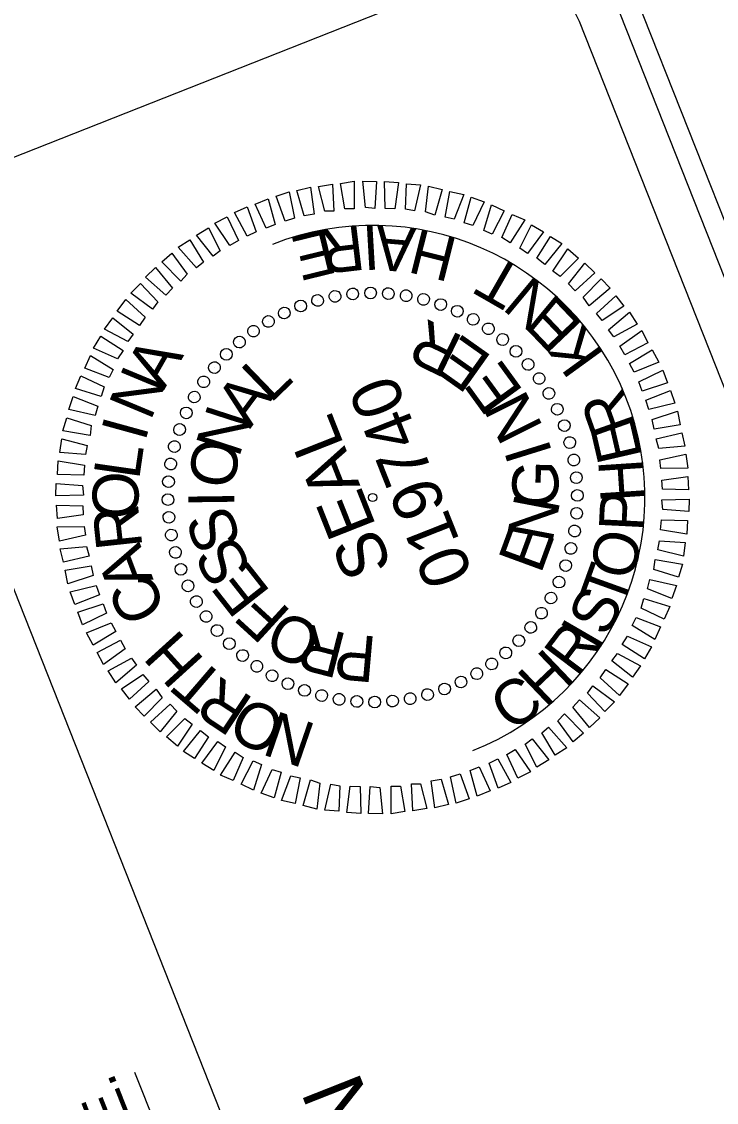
# Model space of a CAD drawing. Extents: x 1247235 to 1260080, y 742320 to 754020.
# Drawn here: x 1251748 to 1252131, y 750320 to 750916 of the extents above; entities that cross this region are included whole.
import ezdxf

# ---------------------------------------------------------------- set-up
doc = ezdxf.new("R2010")
doc.units = 0
for name, color, linetype in [('Scratch_Level_0', 7, 'Continuous'), ('Scratch_Level_1', 7, 'Continuous'), ('Sheet Plot Border Inside CELL', 7, 'Continuous'), ('Sheet Professional Seal CELL', 7, 'Continuous'), ('Sheet Title CELL', 7, 'Continuous')]:
    doc.layers.add(name, color=color, linetype=linetype)

msp = doc.modelspace()

# ---------------------------------------------------------------- linework, layer by layer
at = {"layer": 'Scratch_Level_0'}
msp.add_circle((1251941.28, 750653.8), 2.25, dxfattribs=at)
msp.add_arc((1251941.28, 750653.8), 150.14, 291.57435, 111.57435, dxfattribs=at)
at = {"layer": 'Scratch_Level_1'}
msp.add_line((1251941.28, 750653.8), (1251941.28, 750653.8), dxfattribs=at)
at = {"layer": 'Sheet Plot Border Inside CELL'}
msp.add_lwpolyline([(1254509.01, 744803.37), (1251751.47, 751777.23), (1247336.16, 750031.37), (1250093.7, 743057.51)], close=True, dxfattribs=at)
at = {"layer": 'Sheet Professional Seal CELL'}
for p, q in [((1251920.66, 750764.68), (1251920.66, 750764.68)), ((1251930.2, 750766.27), (1251930.2, 750766.27)), ((1251940.14, 750766.82), (1251940.14, 750766.82)), ((1251950, 750766.36), (1251950, 750766.36)), ((1251959.82, 750765.4), (1251959.82, 750765.4)), ((1251969.42, 750763.15), (1251969.42, 750763.15)), ((1251901.63, 750759.58), (1251901.63, 750759.58)), ((1251911.09, 750762.59), (1251911.09, 750762.59)), ((1251978.97, 750760.4), (1251978.97, 750760.4)), ((1251892.51, 750755.73), (1251892.51, 750755.73)), ((1251987.94, 750756.69), (1251987.94, 750756.69)), ((1251996.95, 750752.26), (1251996.95, 750752.26)), ((1251875.46, 750745.6), (1251875.46, 750745.6)), ((1251884.01, 750750.91), (1251884.01, 750750.91)), ((1252005.08, 750747.01), (1252005.08, 750747.01)), ((1251867.67, 750739.61), (1251867.67, 750739.61)), ((1252013.03, 750740.96), (1252013.03, 750740.96)), ((1252020.44, 750734.45), (1252020.44, 750734.45)), ((1251860.62, 750732.96), (1251860.62, 750732.96)), ((1252027.1, 750727.41), (1252027.1, 750727.41)), ((1251854.12, 750725.55), (1251854.12, 750725.55)), ((1251848.07, 750717.59), (1251848.07, 750717.59)), ((1252033.09, 750719.61), (1252033.09, 750719.61)), ((1251842.81, 750709.46), (1251842.81, 750709.46)), ((1252038.4, 750711.07), (1252038.4, 750711.07)), ((1251838.39, 750700.46), (1251838.39, 750700.46)), ((1252043.21, 750702.57), (1252043.21, 750702.57)), ((1252047.06, 750693.44), (1252047.06, 750693.44)), ((1251834.68, 750691.49), (1251834.68, 750691.49)), ((1251831.93, 750681.93), (1251831.93, 750681.93)), ((1252050.08, 750683.99), (1252050.08, 750683.99)), ((1252052.17, 750674.41), (1252052.17, 750674.41)), ((1251829.67, 750672.33), (1251829.67, 750672.33)), ((1251828.72, 750662.51), (1251828.72, 750662.51)), ((1252053.76, 750664.88), (1252053.76, 750664.88)), ((1251828.26, 750652.66), (1251828.26, 750652.66)), ((1251941.28, 750653.8), (1251941.28, 750653.8)), ((1252054.31, 750654.93), (1252054.31, 750654.93)), ((1252053.85, 750645.08), (1252053.85, 750645.08)), ((1251828.8, 750642.71), (1251828.8, 750642.71)), ((1251830.4, 750633.18), (1251830.4, 750633.18)), ((1252052.89, 750635.26), (1252052.89, 750635.26)), ((1251832.49, 750623.6), (1251832.49, 750623.6)), ((1252050.64, 750625.66), (1252050.64, 750625.66)), ((1251835.5, 750614.15), (1251835.5, 750614.15)), ((1252047.89, 750616.1), (1252047.89, 750616.1)), ((1251839.35, 750605.02), (1251839.35, 750605.02)), ((1252044.17, 750607.13), (1252044.17, 750607.13)), ((1251844.16, 750596.52), (1251844.16, 750596.52)), ((1252039.75, 750598.13), (1252039.75, 750598.13)), ((1251849.48, 750587.98), (1251849.48, 750587.98)), ((1252034.5, 750590), (1252034.5, 750590)), ((1251855.46, 750580.18), (1251855.46, 750580.18)), ((1252028.45, 750582.04), (1252028.45, 750582.04)), ((1251862.12, 750573.14), (1251862.12, 750573.14)), ((1252021.94, 750574.63), (1252021.94, 750574.63)), ((1251869.53, 750566.63), (1251869.53, 750566.63)), ((1252014.9, 750567.98), (1252014.9, 750567.98)), ((1251877.49, 750560.58), (1251877.49, 750560.58)), ((1252007.1, 750561.99), (1252007.1, 750561.99)), ((1251885.62, 750555.33), (1251885.62, 750555.33)), ((1251998.56, 750556.68), (1251998.56, 750556.68)), ((1251894.62, 750550.9), (1251894.62, 750550.9)), ((1251990.06, 750551.86), (1251990.06, 750551.86)), ((1251903.59, 750547.19), (1251903.59, 750547.19)), ((1251913.15, 750544.44), (1251913.15, 750544.44)), ((1251961.9, 750542.91), (1251961.9, 750542.91)), ((1251971.48, 750545), (1251971.48, 750545)), ((1251980.93, 750548.01), (1251980.93, 750548.01)), ((1251922.75, 750542.19), (1251922.75, 750542.19)), ((1251932.56, 750541.23), (1251932.56, 750541.23)), ((1251942.42, 750540.77), (1251942.42, 750540.77)), ((1251952.37, 750541.32), (1251952.37, 750541.32))]:
    msp.add_line(p, q, dxfattribs=at)
for points in [[(1251903.54, 750809.21), (1251899.5, 750823.09), (1251906.95, 750825.07), (1251908.98, 750810.15)], [(1251914.88, 750811.75), (1251911.42, 750825.39), (1251919.11, 750826.73), (1251919.93, 750811.81)], [(1251925.99, 750813), (1251923.59, 750827.05), (1251931.07, 750828.32), (1251931.05, 750813.07)], [(1251937.28, 750813.84), (1251935.92, 750828.3), (1251943.48, 750828.14), (1251942.58, 750813.27)], [(1251948.14, 750813.29), (1251947.82, 750828.17), (1251955.55, 750827.59), (1251953.57, 750813.02)], [(1251959.42, 750812.91), (1251959.93, 750826.91), (1251967.66, 750826.33), (1251964.39, 750811.97)], [(1251970.4, 750811.45), (1251972.05, 750825.65), (1251979.56, 750823.78), (1251975.49, 750809.59)], [(1251882.54, 750802.35), (1251876.54, 750815.71), (1251883.65, 750818.52), (1251887.56, 750804.34)], [(1251893.09, 750806.28), (1251888.13, 750820.05), (1251895.2, 750822.36), (1251898.27, 750807.85)], [(1251981.25, 750808.48), (1251983.9, 750822.59), (1251991.54, 750821.02), (1251986.31, 750807.33)], [(1251991.69, 750805.35), (1251995.55, 750819.45), (1252002.81, 750817), (1251996.61, 750803.91)], [(1251872.16, 750798.01), (1251865.11, 750810.95), (1251872.06, 750814.18), (1251877.02, 750800.41)], [(1252002.53, 750801.17), (1252006.89, 750815.23), (1252013.77, 750811.9), (1252007.21, 750799.14)], [(1251862.62, 750792.78), (1251854.31, 750805.22), (1251861.17, 750808.66), (1251867.31, 750795.6)], [(1252012.59, 750797.16), (1252018.15, 750810.01), (1252025.16, 750806.97), (1252017.09, 750794.34)], [(1251853.32, 750786.93), (1251844.13, 750798.54), (1251850.75, 750802.6), (1251857.21, 750789.92)], [(1252022.38, 750791.35), (1252028.87, 750804.32), (1252035.5, 750800.41), (1252026.67, 750788.45)], [(1251844.27, 750780.44), (1251834.16, 750791.93), (1251840.57, 750795.92), (1251848.08, 750783.65)], [(1252031.8, 750785.88), (1252039.41, 750797.85), (1252045.54, 750793.98), (1252036.13, 750782.27)], [(1251835.55, 750773.13), (1251825.06, 750783.74), (1251830.64, 750788.6), (1251839.11, 750776.95)], [(1252040.68, 750778.75), (1252048.91, 750790.96), (1252054.83, 750785.79), (1252044.76, 750775.76)], [(1252049.25, 750771.74), (1252058.32, 750783.06), (1252063.82, 750777.74), (1252052.96, 750767.88)], [(1251827.2, 750765.47), (1251816.04, 750775.33), (1251821.66, 750780.7), (1251830.98, 750769.38)], [(1251819.86, 750757.73), (1251807.9, 750766.55), (1251813.31, 750771.83), (1251822.84, 750761.81)], [(1252057.29, 750764.27), (1252067.27, 750774.5), (1252072.27, 750769.22), (1252060.61, 750759.53)], [(1252064.69, 750755.34), (1252075.34, 750765.11), (1252079.79, 750759.37), (1252067.89, 750751.52)], [(1251812.8, 750748.65), (1251800.47, 750756.59), (1251805.17, 750763.05), (1251815.83, 750753.23)], [(1251806.38, 750739.82), (1251793.53, 750746.59), (1251798.03, 750752.97), (1251809.36, 750743.9)], [(1252071.38, 750746.37), (1252082.83, 750755.98), (1252087.1, 750749.44), (1252074.17, 750742.39)], [(1252077.65, 750737.24), (1252089.72, 750745.88), (1252093.08, 750739.22), (1252080.27, 750732.46)], [(1251800.7, 750730.31), (1251787.48, 750736.21), (1251791.39, 750742.84), (1251803.72, 750734.9)], [(1252082.88, 750727.69), (1252095.36, 750735.29), (1252099.01, 750728.5), (1252085.49, 750722.92)], [(1251796.06, 750720.01), (1251782.67, 750725.12), (1251785.71, 750732.13), (1251798.17, 750724.47)], [(1252088.06, 750717.64), (1252101.25, 750724.06), (1252103.77, 750717.08), (1252089.84, 750712.54)], [(1251791.72, 750709.58), (1251777.44, 750713.86), (1251780.48, 750720.87), (1251793.28, 750714.8)], [(1251788.37, 750699.07), (1251773.8, 750702.26), (1251776.26, 750709.52), (1251789.73, 750704.2)], [(1252091.83, 750707.51), (1252105.43, 750712.89), (1252107.95, 750705.91), (1252093.6, 750702.41)], [(1251785.49, 750688.01), (1251770.46, 750690.53), (1251772.7, 750697.71), (1251786.18, 750693.6)], [(1252095.34, 750696.8), (1252109.27, 750701.35), (1252110.74, 750693.94), (1252096.48, 750691.45)], [(1251783.07, 750677.61), (1251768.91, 750678.54), (1251769.98, 750686.23), (1251784, 750682.58)], [(1252097.63, 750686.1), (1252111.77, 750689.51), (1252113.45, 750682.19), (1252098.99, 750680.83)], [(1251782.06, 750666.08), (1251767.65, 750666.43), (1251768.01, 750674.08), (1251782.54, 750671.6)], [(1252099.55, 750674.52), (1252113.98, 750677.8), (1252115.12, 750670.03), (1252100.24, 750669.71)], [(1252100.8, 750663.4), (1252115.02, 750665.39), (1252115.49, 750658.08), (1252101.07, 750658.43)], [(1251781.81, 750655.1), (1251766.72, 750654.7), (1251766.92, 750661.55), (1251781.37, 750660.49)], [(1252100.76, 750652.49), (1252115.84, 750652.89), (1252115.65, 750646.04), (1252101.2, 750647.1)], [(1251781.76, 750644.19), (1251767.55, 750642.2), (1251767.08, 750649.51), (1251781.49, 750649.16)], [(1252100.51, 750641.51), (1252114.92, 750641.16), (1252114.55, 750633.51), (1252100.02, 750635.99)], [(1251783.01, 750633.07), (1251768.59, 750629.79), (1251767.45, 750637.56), (1251782.32, 750637.88)], [(1251784.93, 750621.49), (1251770.8, 750618.08), (1251769.11, 750625.4), (1251783.57, 750626.76)], [(1252099.5, 750629.98), (1252113.66, 750629.05), (1252112.58, 750621.36), (1252098.56, 750625.01)], [(1251787.23, 750610.79), (1251773.3, 750606.24), (1251771.82, 750613.65), (1251786.08, 750616.14)], [(1252097.08, 750619.59), (1252112.11, 750617.06), (1252109.87, 750609.88), (1252096.39, 750613.99)], [(1252094.19, 750608.52), (1252108.76, 750605.33), (1252106.31, 750598.07), (1252092.83, 750603.39)], [(1251790.74, 750600.08), (1251777.14, 750594.7), (1251774.62, 750601.69), (1251788.96, 750605.18)], [(1252090.85, 750598.01), (1252105.12, 750593.73), (1252102.09, 750586.72), (1252089.28, 750592.79)], [(1251794.5, 750589.95), (1251781.31, 750583.53), (1251778.79, 750590.51), (1251792.72, 750595.05)], [(1251799.68, 750579.9), (1251787.2, 750572.3), (1251783.55, 750579.09), (1251797.07, 750584.67)], [(1252086.5, 750587.58), (1252099.9, 750582.47), (1252096.86, 750575.46), (1252084.4, 750583.12)], [(1251804.91, 750570.35), (1251792.84, 750561.71), (1251789.49, 750568.37), (1251802.3, 750575.13)], [(1252081.87, 750577.28), (1252095.09, 750571.38), (1252091.18, 750564.75), (1252078.84, 750572.69)], [(1252076.19, 750567.77), (1252089.03, 750561), (1252084.54, 750554.62), (1252073.21, 750563.69)], [(1251811.18, 750561.22), (1251799.74, 750551.61), (1251795.46, 750558.15), (1251808.4, 750565.2)], [(1251817.87, 750552.25), (1251807.22, 750542.48), (1251802.78, 750548.22), (1251814.67, 750556.07)], [(1252069.76, 750558.94), (1252082.1, 750551), (1252077.39, 750544.54), (1252066.74, 750554.36)], [(1252062.71, 750549.86), (1252074.66, 750541.04), (1252069.25, 750535.76), (1252059.72, 750545.78)], [(1251825.28, 750543.32), (1251815.29, 750533.09), (1251810.3, 750538.37), (1251821.95, 750548.06)], [(1251833.31, 750535.86), (1251824.24, 750524.53), (1251818.75, 750529.85), (1251829.61, 750539.71)], [(1252055.36, 750542.12), (1252066.52, 750532.26), (1252060.9, 750526.89), (1252051.59, 750538.21)], [(1251841.89, 750528.84), (1251833.65, 750516.63), (1251827.74, 750521.8), (1251837.81, 750531.83)], [(1252047.02, 750534.47), (1252057.51, 750523.85), (1252051.93, 750518.99), (1252043.45, 750530.64)], [(1251850.76, 750521.71), (1251843.15, 750509.74), (1251837.02, 750513.61), (1251846.43, 750525.32)], [(1252038.3, 750527.15), (1252048.41, 750515.66), (1252042, 750511.67), (1252034.48, 750523.94)], [(1251860.18, 750516.24), (1251853.7, 750503.27), (1251847.07, 750507.18), (1251855.89, 750519.14)], [(1252029.25, 750520.66), (1252038.44, 750509.05), (1252031.82, 750504.99), (1252025.35, 750517.67)], [(1251869.98, 750510.43), (1251864.41, 750497.59), (1251857.4, 750500.62), (1251865.48, 750513.25)], [(1252019.95, 750514.81), (1252028.26, 750502.37), (1252021.39, 750498.93), (1252015.26, 750511.99)], [(1251880.03, 750506.42), (1251875.67, 750492.36), (1251868.79, 750495.69), (1251875.36, 750508.45)], [(1252010.4, 750509.58), (1252017.45, 750496.64), (1252010.51, 750493.41), (1252005.55, 750507.18)], [(1251890.88, 750502.24), (1251887.02, 750488.14), (1251879.76, 750490.59), (1251885.95, 750503.68)], [(1251989.48, 750501.31), (1251994.44, 750487.54), (1251987.37, 750485.23), (1251984.29, 750499.74)], [(1252000.02, 750505.24), (1252006.03, 750491.88), (1251998.92, 750489.07), (1251995, 750503.25)], [(1251901.31, 750499.11), (1251898.66, 750485), (1251891.02, 750486.57), (1251896.26, 750500.26)], [(1251912.16, 750496.14), (1251910.52, 750481.94), (1251903.01, 750483.81), (1251907.07, 750498)], [(1251923.15, 750494.68), (1251922.63, 750480.68), (1251914.9, 750481.26), (1251918.18, 750495.62)], [(1251967.69, 750495.84), (1251971.15, 750482.2), (1251963.45, 750480.86), (1251962.63, 750495.78)], [(1251979.02, 750498.38), (1251983.06, 750484.5), (1251975.62, 750482.52), (1251973.59, 750497.45)], [(1251934.42, 750494.3), (1251934.74, 750479.42), (1251927.01, 750480), (1251928.99, 750494.57)], [(1251945.29, 750493.76), (1251946.65, 750479.29), (1251939.09, 750479.45), (1251939.98, 750494.32)], [(1251956.57, 750494.59), (1251958.98, 750480.54), (1251951.5, 750479.27), (1251951.51, 750494.52)]]:
    msp.add_lwpolyline(points, close=True, dxfattribs=at)
for centre, major_axis in [((1251930.32, 750766.12), (-0.31, 3.22)), ((1251940.15, 750766.65), (-0.03, 3.24)), ((1251949.99, 750766.32), (0.25, 3.23)), ((1251901.62, 750759.46), (-1.14, 3.03)), ((1251910.98, 750762.51), (-0.87, 3.12)), ((1251920.57, 750764.74), (-0.59, 3.18)), ((1251959.77, 750765.13), (0.53, 3.2)), ((1251969.4, 750763.1), (0.81, 3.14)), ((1251978.82, 750760.23), (1.08, 3.06)), ((1251892.56, 750755.6), (-1.4, 2.92)), ((1251987.95, 750756.55), (1.34, 2.95)), ((1251883.88, 750750.96), (-1.65, 2.79)), ((1251996.73, 750752.1), (1.59, 2.82)), ((1251875.63, 750745.59), (-1.88, 2.64)), ((1252005.09, 750746.89), (1.83, 2.67)), ((1251867.87, 750739.52), (-2.11, 2.46)), ((1252012.96, 750740.97), (2.06, 2.5)), ((1251860.68, 750732.8), (-2.31, 2.27)), ((1252020.28, 750734.4), (2.27, 2.31)), ((1251854.1, 750725.47), (-2.5, 2.06)), ((1252027.01, 750727.2), (2.46, 2.11)), ((1252033.08, 750719.45), (2.64, 1.88)), ((1251848.19, 750717.6), (-2.67, 1.83)), ((1251842.98, 750709.24), (-2.82, 1.59)), ((1252038.45, 750711.2), (2.79, 1.65)), ((1251838.52, 750700.46), (-2.95, 1.34)), ((1252043.09, 750702.51), (2.92, 1.4)), ((1251834.85, 750691.33), (-3.06, 1.08)), ((1252046.94, 750693.46), (3.03, 1.14)), ((1252050, 750684.1), (3.12, 0.87)), ((1251831.98, 750681.91), (-3.14, 0.81)), ((1251829.95, 750672.28), (-3.2, 0.53)), ((1252052.23, 750674.51), (3.18, 0.59)), ((1252053.61, 750664.76), (3.22, 0.31)), ((1251828.76, 750662.5), (-3.23, 0.25)), ((1251828.43, 750652.66), (-3.24, -0.03)), ((1252054.14, 750654.93), (3.24, 0.03)), ((1251828.96, 750642.83), (-3.22, -0.31)), ((1252053.81, 750645.09), (3.23, -0.25)), ((1252052.62, 750635.31), (3.2, -0.53)), ((1251830.34, 750633.08), (-3.18, -0.59)), ((1251832.57, 750623.49), (-3.12, -0.87)), ((1252050.58, 750625.68), (3.14, -0.81)), ((1251835.62, 750614.13), (-3.03, -1.14)), ((1252047.72, 750616.26), (3.06, -1.08)), ((1251839.48, 750605.08), (-2.92, -1.4)), ((1252044.04, 750607.13), (2.95, -1.34)), ((1251844.11, 750596.39), (-2.79, -1.65)), ((1252039.58, 750598.35), (2.82, -1.59)), ((1251849.49, 750588.14), (-2.64, -1.88)), ((1252034.38, 750589.99), (2.67, -1.83)), ((1252028.46, 750582.12), (2.5, -2.06)), ((1251855.56, 750580.39), (-2.46, -2.11)), ((1252021.88, 750574.8), (2.31, -2.27)), ((1251862.28, 750573.2), (-2.27, -2.31)), ((1251869.61, 750566.62), (-2.06, -2.5)), ((1252014.69, 750568.07), (2.11, -2.46)), ((1251877.48, 750560.7), (-1.83, -2.67)), ((1252006.94, 750562), (1.88, -2.64)), ((1251885.84, 750555.49), (-1.59, -2.82)), ((1251894.61, 750551.04), (-1.34, -2.95)), ((1251990, 750551.99), (1.4, -2.92)), ((1251998.69, 750556.63), (1.65, -2.79)), ((1251903.75, 750547.36), (-1.08, -3.06)), ((1251971.58, 750545.08), (0.87, -3.12)), ((1251980.94, 750548.13), (1.14, -3.03)), ((1251913.17, 750544.49), (-0.81, -3.14)), ((1251922.8, 750542.46), (-0.53, -3.2)), ((1251932.57, 750541.27), (-0.25, -3.23)), ((1251942.41, 750540.94), (0.03, -3.24)), ((1251952.25, 750541.47), (0.31, -3.22)), ((1251961.99, 750542.85), (0.59, -3.18))]:
    msp.add_ellipse(centre, major_axis=major_axis, ratio=0.999708, dxfattribs=at)
at = {"layer": 'Sheet Title CELL'}
for p, q in [((1251996.89, 750941.65), (1251327.33, 750676.9)), ((1252025.66, 749889.55), (1251662.01, 750809.23)), ((1251975.69, 749918.19), (1251810.22, 750336.66))]:
    msp.add_line(p, q, dxfattribs=at)
for points in [[(1254226.97, 745485.45), (1251778.03, 751678.86)], [(1252385.84, 750080.36), (1252055.28, 750916.35)]]:
    msp.add_lwpolyline(points, dxfattribs=at)
msp.add_arc((1252013.43, 750899.8), 45, 21.57435, 111.57435, dxfattribs=at)

# ---------------------------------------------------------------- texts
at = {"layer": 'Sheet Professional Seal CELL'}
for s, height, rotation, p in [('E', 24.75, 193.75688, (1251916.87, 750802.39)), ('R', 24.75, 186.83044, (1251934.97, 750804.25)), ('I', 24.75, 183.30997, (1251944.22, 750804.35)), ('A', 24.75, 175.12418, (1251965.63, 750802.4)), ('H', 24.75, 165.87938, (1251989.18, 750796.56)), ('T', 24.75, 150.13746, (1252026.12, 750778.21)), ('N', 24.75, 140.20574, (1252046.31, 750761.71)), ('E', 24.75, 133.62276, (1252057.99, 750748.96)), ('R', 25.37, 154.05576, (1251992.23, 750742.17)), ('K', 24.75, 125.95215, (1252069.65, 750732.53)), ('E', 25.37, 144.69844, (1252007.94, 750731.2)), ('A', 25.37, 60.1915, (1251826.24, 750712.83)), ('L', 25.38, 43.9752, (1251884.87, 750705.28)), ('E', 25.37, 125.98611, (1252024.87, 750712.25)), ('N', 25.37, 67.39326, (1251818.78, 750695.6)), ('A', 25.38, 53.33462, (1251873.66, 750691.42)), ('019740', 26.992, 111.57435, (1251996.91, 750611.11)), ('N', 25.37, 116.63074, (1252035.57, 750692.53)), ('R', 24.75, 109.58056, (1252086.63, 750693.16)), ('N', 25.37, 72.05096, (1251867.5, 750675.19)), ('SEAL', 26.992, 111.57435, (1251952.29, 750615.57)), ('I', 25.37, 74.59449, (1251815.85, 750684.04)), ('E', 24.75, 102.99758, (1252090.19, 750676.24)), ('L', 25.37, 81.79522, (1251812.51, 750663.12)), ('O', 25.37, 81.40783, (1251864.67, 750657.86)), ('I', 25.37, 107.27555, (1252040.49, 750678.26)), ('G', 25.37, 88.56459, (1252043.37, 750647.71)), ('H', 24.75, 93.75278, (1252091.86, 750652.02)), ('O', 25.37, 88.99551, (1251812.05, 750641.65)), ('P', 24.75, 87.1698, (1252090.66, 750634.77)), ('I', 25.37, 90.76395, (1251865.05, 750648.33)), ('N', 25.37, 79.20831, (1252040.25, 750628.08)), ('R', 25.37, 96.19545, (1251814.45, 750626.39)), ('S', 25.37, 109.47475, (1251869.24, 750629.18)), ('E', 25.37, 69.85124, (1252033.91, 750611.06)), ('O', 24.75, 76.46529, (1252084.53, 750607.36)), ('A', 25.37, 110.59467, (1251820.56, 750608.48)), ('S', 25.37, 118.82996, (1251875.4, 750614.2)), ('E', 25.37, 128.18542, (1251885.51, 750601.5)), ('T', 24.75, 70.16853, (1252078.57, 750591.92)), ('C', 25.37, 117.79422, (1251828.35, 750592.45)), ('S', 24.75, 63.38519, (1252070.3, 750576.14)), ('F', 25.37, 137.54138, (1251897.08, 750590.59)), ('O', 25.37, 156.25559, (1251914.88, 750581.66)), ('I', 24.75, 59.86473, (1252065.29, 750568.37)), ('H', 25.37, 132.19383, (1251849.3, 750563.95)), ('R', 25.38, 165.614, (1251928.03, 750578.39)), ('R', 24.75, 52.93828, (1252054.08, 750554.03)), ('P', 25.38, 174.97324, (1251944.07, 750576.99)), ('H', 24.75, 43.69349, (1252036.59, 750537.21)), ('T', 25.37, 139.39412, (1251861.58, 750553.08)), ('R', 25.37, 146.59486, (1251876.41, 750542.49)), ('C', 24.75, 34.82077, (1252017.47, 750523.9)), ('O', 25.37, 153.79609, (1251895.1, 750533.19)), ('N', 25.37, 160.99785, (1251911.04, 750528.36))]:
    msp.add_text(s, height=height, rotation=rotation, dxfattribs=at).set_placement(p)
at = {"layer": 'Sheet Title CELL'}
for s, height, p in [('P.E.', 22.5, (1251818.82, 750284.33)), ('ROADWAY DESIGN', 33.7473, (1252086.87, 749948.9))]:
    msp.add_text(s, height=height, rotation=111.57435, dxfattribs=at).set_placement(p)

doc.saveas('drawing.dxf')
